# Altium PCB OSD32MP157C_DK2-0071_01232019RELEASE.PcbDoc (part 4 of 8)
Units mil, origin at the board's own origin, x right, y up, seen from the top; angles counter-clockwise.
Board outline 3976.38 x 2795.28 mil, 6 copper layers (Top Layer, Signal Layer 1, Signal Layer 2, Signal Layer 3, Signal Layer 4, Bottom Layer), stack 61.268 mil thick; 404 components, 418 nets, 1720 pads, 1233 vias.
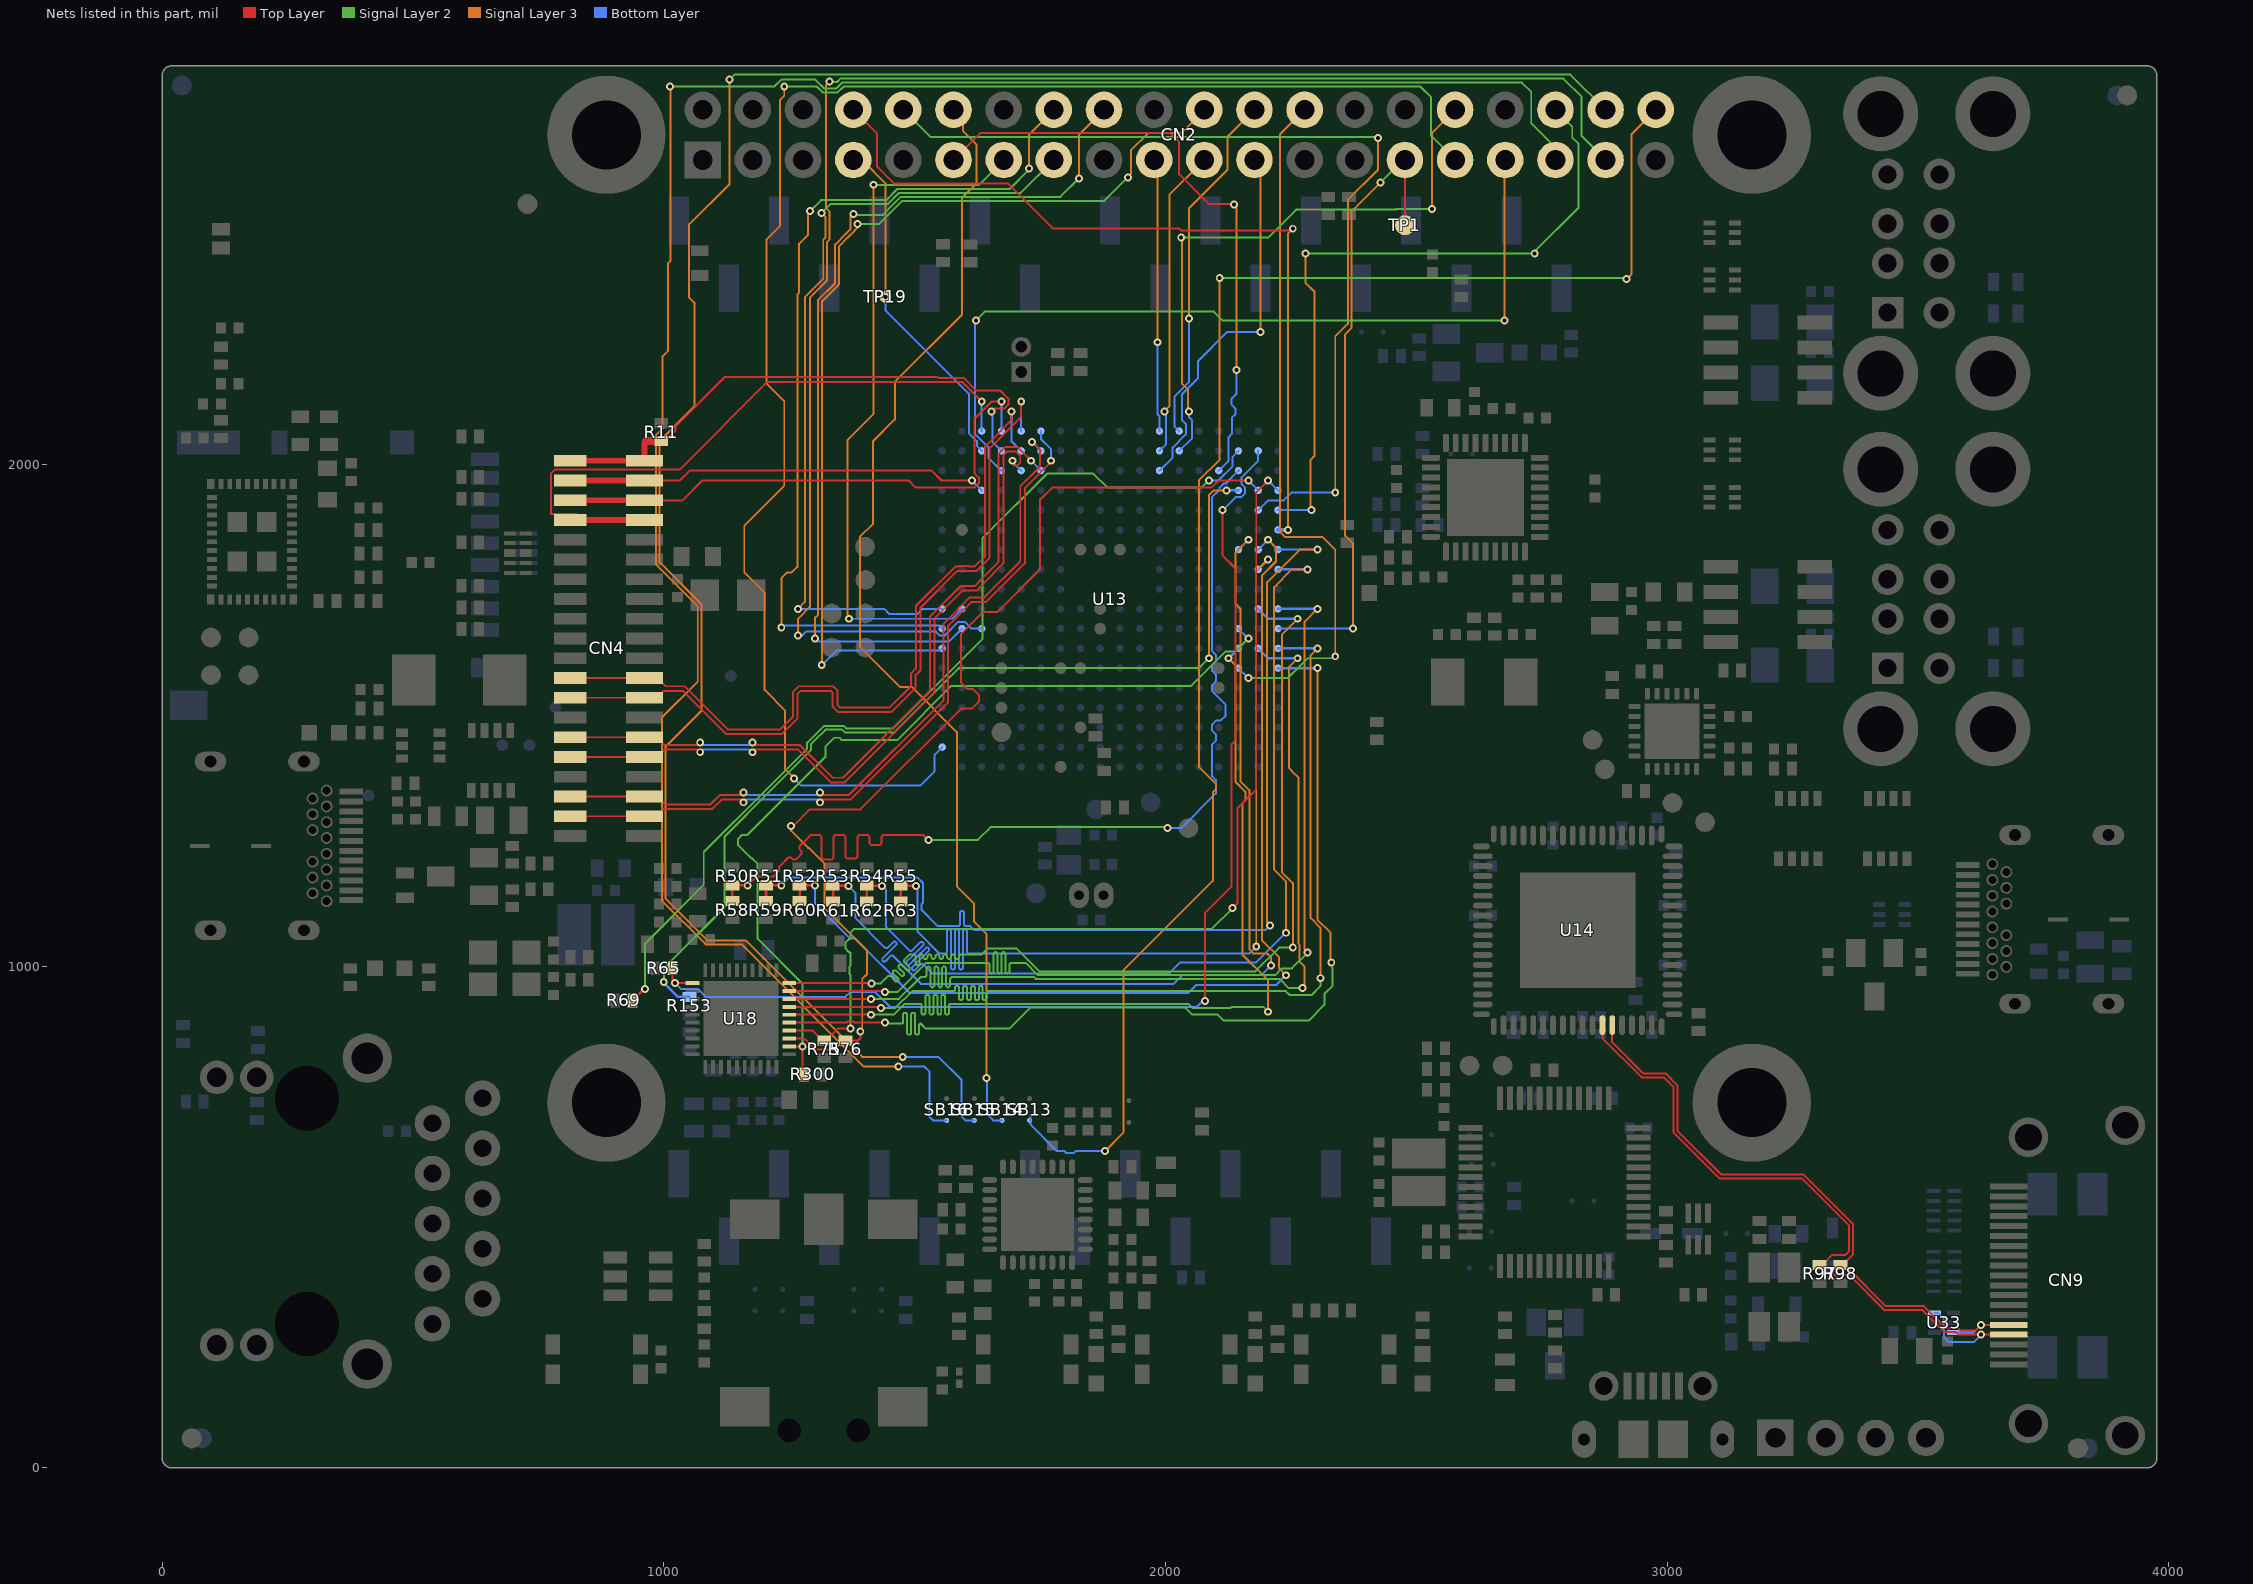
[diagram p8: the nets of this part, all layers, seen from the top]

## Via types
v1: diameter 15.75, hole 7.87, Top Layer to Bottom Layer, tented both sides, 803 vias
v2: diameter 23.62, hole 11.81, Top Layer to Bottom Layer, tented both sides, 417 vias
v3: diameter 15.75, hole 7.87, Top Layer to Bottom Layer, 13 vias

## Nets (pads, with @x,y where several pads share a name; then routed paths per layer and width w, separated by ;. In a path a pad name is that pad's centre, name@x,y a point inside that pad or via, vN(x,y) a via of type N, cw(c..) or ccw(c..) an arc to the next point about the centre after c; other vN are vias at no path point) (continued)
DSCL: CN9.15 R98.1 U14.49 U33.3 | length 1273.2
  Top Layer w3.94: U14.49@2890.75,882.87 2890.75,848.43 2952.76,786.42 2997.05,786.42 3020.67,762.8 3020.67,672.55 3108.58,584.65 3272.5,584.65 3371.06,486.08 3371.06,426.18 3349.41,404.53 R98.1@3345.47,404.53 3345.47,396.65 3362.51,396.65 3436.33,322.83 3512.12,322.83 3556.41,278.54 3580.03,278.54 3584.95,273.62 3614.17,273.62 v1(3625.98,285.43) CN9.15@3681.1,285.43
  Bottom Layer w3.94: U33.3@3570.87,269.69 3610.24,269.69 v1(3625.98,285.43)
DSDA: CN9.16 R97.1 U14.48 U33.6 | length 1425.2
  Top Layer w3.94: U14.48@2871.06,882.87 2871.06,856.98 2949.5,778.54 2993.79,778.54 3012.8,759.53 3012.8,669.29 3105.31,576.77 3269.24,576.77 3363.19,482.82 3363.19,432.09 3355.31,424.21 3328.74,424.21 3309.06,404.53 R97.1@3304.13,404.53 3322.83,385.83 3362.2,385.83 3433.07,314.96 3508.86,314.96 3553.15,270.67 3576.77,270.67 3581.69,265.75 v1(3625.98,265.75) CN9.16@3681.1,265.75
  Bottom Layer w3.94: U33.6@3533.46,309.06 3539.85,309.06 3552.17,296.74 3552.17,260.83 3562.01,250.98 3611.22,250.98 v1(3625.98,265.75)
DSI_CK_N: CN4.9 CN4.10 U13.P16 | length 1494.8
  Top Layer w3.94: CN4.10@813.98,1417.32 986.35,1417.32 1000.94,1431.92 1067.61,1431.92 v1(1072.65,1426.88) ; v1(1177.04,1426.79) 1182.25,1432 1267.79,1432 1332.86,1366.93 1361.02,1366.93 1539.37,1545.28 1539.37,1692.91 1595.28,1748.82 1623.63,1748.82 1637.01,1762.2 1637.01,1762.99 1677.17,1803.15 1677.17,2018.5 1685.04,2026.38 1701.97,2026.38 1710.63,2017.72 1710.63,2003.94 1704.72,1998.03 1698.82,1998.03 1696.85,2000 1696.85,2005.91 v1(1694.88,2007.87)
  Bottom Layer w3.54: v1(1072.65,1426.88) 1078.06,1432.3 1171.53,1432.3 v1(1177.04,1426.79)
  Bottom Layer w3.94: v1(1694.88,2007.87) 1694.88,2005.91 U13.P16@1712.6,1988.19
DSI_CK_P: CN4.11 CN4.12 U13.N16 | length 1493.7
  Top Layer w3.94: CN4.12@813.98,1456.69 CN4.11@961.61,1456.69 985.98,1456.69 1001.69,1440.98 1067.06,1440.98 v1(1072.65,1446.57) ; v1(1177.04,1446.47) 1182.45,1441.06 1271.54,1441.06 1336.61,1375.98 1357.27,1375.98 1530.31,1549.03 1530.31,1696.66 1591.52,1757.87 1619.88,1757.87 1627.95,1765.95 1627.95,1766.74 1667.32,1806.11 1667.32,2021.47 1673.23,2027.37 1673.23,2027.56 1681.1,2035.43 1704.72,2035.43 v1(1732.28,2007.87) v1@1733.27,2006.89
  Bottom Layer w3.54: v1@1171.72,1441.16 v1(1177.04,1446.47)
  Bottom Layer w3.94: v1(1072.65,1446.57) 1078.06,1441.16 v1@1171.72,1441.16 ; v1(1732.28,2007.87) v1@1736.22,2003.94 ; v1@1736.22,2009.84 1736.22,2007.87 v1@1736.22,2003.94 ; U13.N16@1751.97,1988.19 v1@1736.22,2003.94
DSI_D0_N: CN4.15 CN4.16 U13.P18 | length 1587.1
  Top Layer w3.94: CN4.16@813.98,1535.43 CN4.15@961.61,1535.43 986.33,1535.43 1000.2,1549.3 1037.7,1549.3 1123.61,1463.39 1236.03,1463.39 1266.93,1494.28 1266.93,1543.49 1272.73,1549.3 1332.59,1549.3 1336.61,1545.28 1336.61,1517.72 1347.64,1506.69 1453.54,1506.69 1501.97,1555.12 1501.97,1580.51 1511.81,1590.35 1511.81,1714.57 1585.43,1788.19 1623.63,1788.19 1649.61,1814.16 1649.61,2032.47 1712.6,2095.46 v1(1712.6,2125.98)
  Bottom Layer w3.94: U13.P18@1712.6,2066.93 v1(1712.6,2125.98)
DSI_D0_P: CN4.17 CN4.18 U13.P17 | length 1578.8
  Top Layer w3.94: CN4.18@813.98,1574.8 CN4.17@961.61,1574.8 987.5,1574.8 1003.95,1558.35 1041.45,1558.35 1127.36,1472.44 1232.28,1472.44 1257.87,1498.03 1257.87,1547.24 1268.98,1558.35 1338.58,1558.35 1338.58,1557.09 1346.46,1549.21 1346.46,1520.68 1351.39,1515.75 1449.79,1515.75 1492.91,1558.87 1492.91,1584.26 1502.76,1594.1 1502.76,1718.32 1581.68,1797.24 1587.59,1797.24 1588.18,1797.84 1607.87,1797.84 1608.47,1797.24 1619.88,1797.24 1640.55,1817.91 1640.55,2036.22 1692.91,2088.58 v1(1692.91,2106.3)
  Bottom Layer w3.94: v1(1692.91,2106.3) 1692.91,2047.24 U13.P17@1712.6,2027.56
DSI_D1_N: CN4.3 CN4.4 U13.N18 | length 1506
  Top Layer w3.94: CN4.4@813.98,1299.21 CN4.3@961.61,1299.21 985.58,1299.21 1000.18,1313.81 1096.88,1313.81 1115.43,1332.36 1153.97,1332.36 v1(1159.28,1327.04) ; v1(1311.53,1327.04) 1317.17,1332.68 1373.04,1332.68 1566.93,1526.56 1566.93,1679.13 1614.17,1726.38 1642.73,1726.38 1719.68,1803.34 1719.68,1952.94 1771.65,2004.91 v1(1771.65,2007.87)
  Bottom Layer w3.94: v1(1159.28,1327.04) 1164.6,1332.36 1306.22,1332.36 v1(1311.53,1327.04) ; U13.N18@1751.97,2066.93 1751.97,2051.18 1771.65,2031.5 v1(1771.65,2007.87)
DSI_D1_P: CN4.5 CN4.6 U13.N17 | length 1493.3
  Top Layer w3.94: CN4.6@813.98,1338.58 CN4.5@961.61,1338.58 986.12,1338.58 1001.83,1322.87 1093.13,1322.87 1111.68,1341.41 1153.97,1341.41 v1(1159.28,1346.73) ; v1(1311.53,1346.73) 1316.53,1341.73 1369.29,1341.73 1557.87,1530.31 1557.87,1682.88 1610.42,1735.43 1638.98,1735.43 1710.63,1807.09 1710.63,1956.69 1750,1996.06 1750,2029.53 v1(1734.25,2045.28) v1@1732.28,2047.24
  Bottom Layer w3.94: v1(1159.28,1346.73) 1164.6,1341.41 1306.22,1341.41 v1(1311.53,1346.73) ; v1@1732.28,2047.24 v1(1734.25,2045.28) U13.N17@1751.97,2027.56
DSI_LCD_BL_CTRL: CN4.37 CN4.38 U13.T15 | length 844.3
  Top Layer w3.94: CN4.37@961.61,1968.5 1032.17,1968.5 1051.86,1988.19 1533.96,1988.19 1553.64,1968.5 v1(1614.17,1968.5)
  Top Layer w11.81: CN4.38@813.98,1968.5 CN4.37@961.61,1968.5
  Bottom Layer w3.94: v1(1614.17,1968.5) U13.T15@1633.86,1948.82
DSI_LCD_INT: CN4.33 CN4.34 U13.T18 | length 1305.8
  Top Layer w3.94: CN4.34@813.98,1889.76 826.38,1902.17 775.59,1902.17 775.59,1982.76 782.99,1990.16 1031.5,1990.16 1206.69,2165.35 1594.49,2165.35 v1(1633.86,2125.98)
  Top Layer w11.81: CN4.34@813.98,1889.76 CN4.33@961.61,1889.76
  Bottom Layer w3.94: U13.T18@1633.86,2066.93 v1(1633.86,2125.98)
DSI_RESET: CN4.39 CN4.40 R11.2 U13.R17 | length 1124.2
  Top Layer w3.94: R11.2@995.08,2047.24 1002.37,2047.24 1023.62,2068.5 1023.62,2076.77 1122.05,2175.2 1545.28,2175.2 1547.24,2173.23 1597.75,2173.23 1623.34,2147.64 1671.26,2147.64 1687.01,2131.89 1687.01,2120.28 1678.74,2112.01 1659.25,2112.01 v1(1653.54,2106.3)
  Top Layer w11.81: CN4.40@813.98,2007.87 CN4.39@961.61,2007.87 961.61,2044.29 964.57,2047.24
  Top Layer w15.75: 964.57,2047.24 R11.2@995.08,2047.24
  Bottom Layer w3.94: v1(1653.54,2106.3) 1655.02,2104.82 1655.02,2045.77 U13.R17@1673.23,2027.56
DSI_TE: CN4.35 CN4.36 U13.R18 | length 1098.4
  Top Layer w3.94: CN4.35@961.61,1929.13 1037.4,1929.13 1076.77,1968.5 1487.98,1968.5 1501.77,1954.72 1619.88,1954.72 1627.95,1962.8 1627.95,1974.21 1619.88,1982.28 1619.88,2092.12 1653.74,2125.98 v1(1673.23,2125.98)
  Top Layer w11.81: CN4.36@813.98,1929.13 CN4.35@961.61,1929.13
  Bottom Layer w3.94: U13.R18@1673.23,2066.93 v1(1673.23,2125.98)
ETH_CLK: R69.2 U13.C17 | length 1915.6
  Top Layer w5.12: R69.2@937.99,932.09 960.63,954.72 v1(962.6,954.72)
  Signal Layer 2 w3.94: v1(962.6,954.72) 962.6,1045.27 1079.72,1162.4 1079.72,1228 1205.12,1353.39 1285.83,1434.1 1285.83,1445.81 1319.54,1479.53 1358.56,1479.53 1363.68,1474.41 1457.11,1474.41 1635.83,1653.12 1635.83,1854.13 1763.98,1982.28 1856.1,1982.28 1858.07,1980.31 1858.47,1980.31 1884.06,1954.72 2072.83,1954.72 v1(2086.61,1968.5)
  Bottom Layer w3.94: v1(2086.61,1968.5) 2105.41,1968.5 2133.86,1996.96 2133.86,2015.75 U13.C17@2145.67,2027.56
ETH_CLK125: R153.1 U13.C15 | length 1916.8
  Signal Layer 2 w3.94: v1(1000,968.5) 1000,996.26 1121.06,1117.32 1121.06,1258.76 1212.6,1350.29 1293.46,1431.15 1293.31,1431.3 1293.31,1442.72 1301.38,1450.79 1322.64,1472.05 1355.46,1472.05 1360.97,1466.54 1459.82,1466.54 1587.77,1594.49 2066.93,1594.49 v1(2086.61,1614.17)
  Signal Layer 3 w3.94: v1(2086.61,1614.17) 2086.61,1938.98 2096.46,1948.82 v1(2122.05,1948.82)
  Bottom Layer w5.12: v1(1000,968.5) 1000,967.17 1028.2,938.98 R153.1@1051.18,938.98 ; v1(2122.05,1948.82) U13.C15@2145.67,1948.82
ETH_GTX_CLK: U13.B9 U18.20 | length 2038.4
  Top Layer w3.94: U18.20@1250,966.54 1413.89,966.54 v1(1414.28,966.14)
  Signal Layer 2 w3.94: v1(1414.28,966.14) 1432.68,966.14 1440.94,974.41 1443.73,977.19 1447.35,980.81 1451.25,980.81 1462.38,969.68 1466.28,969.68 1467.95,971.35 1467.95,975.24 1456.81,986.38 1456.81,990.28 1458.48,991.95 1462.38,991.95 1473.52,980.81 1477.41,980.81 1479.08,982.48 1479.08,986.38 1467.95,997.52 1467.95,1001.41 1469.62,1003.08 1473.52,1003.08 1484.65,991.95 1488.55,991.95 1490.22,993.62 1490.22,997.52 1479.08,1008.65 1479.08,1012.55 1482.7,1016.17 1488.27,1021.74 1490.16,1023.62 1494.09,1023.62 1499.21,1023.62 1501.97,1020.87 1501.97,1005.12 1504.72,1002.36 1507.09,1002.36 1509.84,1005.12 1509.84,1020.87 1512.6,1023.62 1514.96,1023.62 1517.72,1020.87 1517.72,1017.31 1520.47,1014.55 1522.83,1014.55 1525.59,1017.31 1525.59,1020.87 1528.35,1023.62 1530.71,1023.62 1533.46,1020.87 1533.46,1017.32 1536.22,1014.57 1538.58,1014.57 1541.34,1017.32 1541.34,1020.87 1544.09,1023.62 1546.46,1023.62 1549.21,1020.87 1549.21,1017.32 1551.97,1014.57 1554.33,1014.57 1557.09,1017.32 1557.09,1020.87 1559.84,1023.62 1562.2,1023.62 1564.96,1020.87 1564.96,1017.32 1567.72,1014.57 1570.08,1014.57 1572.83,1017.32 1572.83,1020.87 1575.59,1023.62 1577.95,1023.62 1580.71,1020.87 1580.71,1017.32 1583.46,1014.57 1585.83,1014.57 1588.58,1017.32 1588.58,1020.87 1591.34,1023.62 1596.46,1023.62 1633.86,1023.62 1646.06,1035.83 1703.1,1035.83 1748.77,990.16 2179.53,990.16 2226.77,1037.4 v1(2253.94,1037.4)
  Signal Layer 3 w3.94: v1(2253.94,1037.4) 2253.94,1166.09 2232.28,1187.74 2232.28,1661.42 v1(2263.78,1692.91)
  Bottom Layer w5.12: U13.B9@2185.04,1712.6 2204.72,1692.91 v1(2263.78,1692.91)
ETH_MDC: R76.1 U13.B15 U18.13 | length 2091.9
  Top Layer w3.94: U18.13@1250,856.3 1276.57,856.3 1278.54,854.33 1282.28,854.33 1301.97,834.65 1340.55,834.65 1358.27,852.36 R76.1@1365.16,852.36 ; v1@1257.87,1279.53 1291.34,1312.99 1391.73,1312.99 1592.72,1513.98 1614.17,1513.98 1627.95,1527.76 1627.95,1541.14 1615.94,1553.15 1605.2,1553.15 1592.91,1565.44 1592.91,1662.99 1636.62,1706.69 1665.35,1706.69 1750,1791.34 1750,1929.75 1774.97,1954.72 2092.32,1954.72 2106.1,1968.5 v1(2165.35,1968.5) ; R76.1@1362.2,852.36 1387.8,852.36 1391.73,856.3 v1(1391.73,870.08)
  Signal Layer 3 w3.94: v1(1253.94,1279.53) 1253.94,1269.88 1287.6,1236.22 1288.83,1236.22 1320.87,1204.19 1320.87,1115.94 1405.51,1031.3 1405.51,984.79 1395.67,974.95 1395.67,874.02 v1(1391.73,870.08)
  Bottom Layer w3.94: v1(2165.35,1968.5) U13.B15@2185.04,1948.82
ETH_MDINT: R65.1 U13.B17 U18.31 | length 2331.4
  Top Layer w3.94: R65.1@1017.72,996.06 1017.72,971.46 v1(1022.64,966.54) U18.31@1057.09,966.54 ; v1(2078.76,931.1) 2078.76,1106.12 2131.89,1159.25 2131.89,1443.11 2139.76,1450.99 2139.76,1793.11 2114.17,1818.7 v1(2114.17,1909.45)
  Bottom Layer w3.94: v1(1022.64,966.54) 1034.25,954.92 1067.41,954.92 1083.35,938.98 1362.2,938.98 1372.05,948.82 1421.46,948.82 1450.99,919.29 2063.01,919.29 2076.79,933.07 v1(2078.76,931.1) ; v1(2114.17,1909.45) 2114.17,1909.54 2140.17,1935.53 2151.17,1935.53 2158.96,1943.32 2158.96,1954.32 2151.57,1961.7 2151.57,1974.41 2185.04,2007.87 U13.B17@2185.04,2027.56 U13.B17@2185.04,2028.35
ETH_MDIO: R75.1 U13.A15 U18.14 | length 2034.6
  Top Layer w3.94: U18.14@1250,872.05 1297.24,872.05 1316.93,852.36 R75.1@1319.88,852.36 1322.83,852.36 1346.45,875.98 v1(1372.04,875.98) ; v1(2133.86,1116.14) 2143.7,1125.98 2143.7,1314.96 2167.32,1338.58 2181.1,1352.36 2181.1,1944.88 v1(2204.72,1968.5)
  Signal Layer 2 w3.94: v1(1372.04,875.98) 1372.04,982.82 1370.08,984.79 1370.08,999.46 1372.04,1001.43 1372.04,1027.56 1370.28,1027.56 1362.2,1035.63 1362.2,1047.05 1370.28,1055.12 1372.04,1055.12 1372.04,1066.93 1379.92,1074.8 2092.72,1074.8 2133.86,1115.94 v1(2133.86,1116.14)
  Bottom Layer w3.94: v1(2204.72,1968.5) U13.A15@2224.41,1948.82
ETH_NRST: R300.2 U13.C8 U18.12 | length 1778.1
  Top Layer w3.94: U18.12@1250,840.55 v1(1276.57,840.55) 1276.57,787.4 R300.2@1279.53,784.45
  Signal Layer 2 w3.94: v1(1276.57,840.55) 1276.57,965.16 1187.01,1054.72 1187.01,1204.19 1176.63,1214.57 1175.39,1214.57 1147.64,1242.32 1147.64,1253.74 1155.71,1261.81 1166.34,1261.81 1322.83,1418.3 1322.83,1438.78 1339.76,1455.71 1350.64,1455.71 1355.17,1451.18 1465.62,1451.18 1573.49,1559.06 2051.38,1559.06 2120.28,1627.95 2139.76,1627.95 v1(2165.35,1653.54)
  Bottom Layer w3.94: U13.C8@2145.67,1673.23 v1(2165.35,1653.54)
ETH_RX_CLK: R50.2 R58.1 U13.C16 | length 2029.5
  Top Layer w3.94: v1(1167.32,1161.42) 1185.04,1179.13 1218.19,1179.13 1230.01,1190.94 1230.01,1198.51 1234.07,1202.57 1248.45,1216.96 1253.53,1216.96 1257.69,1212.79 1262.77,1212.79 1274.62,1224.64 1274.62,1229.72 1270.46,1233.88 1270.46,1238.96 1284.84,1253.35 1293.31,1261.81 1310.66,1261.81 1314.25,1258.22 1314.25,1216.38 1317.84,1212.79 1334.6,1212.79 1338.19,1216.38 1338.19,1258.22 1341.78,1261.81 1358.54,1261.81 1362.13,1258.22 1362.13,1218.16 1365.72,1214.57 1382.47,1214.57 1386.06,1218.16 1386.06,1258.22 1389.65,1261.81 1406.41,1261.81 1410,1258.22 1410,1245.22 1413.59,1241.63 1430.35,1241.63 1433.94,1245.22 1433.94,1258.22 1437.53,1261.81 1457.87,1261.81 1481.81,1261.81 1505.75,1261.81 1517.72,1261.81 v1(1527.56,1251.97)
  Top Layer w5.12: R58.1@1136.81,1129.92 R50.2@1136.81,1161.42 v1(1167.32,1161.42)
  Signal Layer 2 w3.94: v1(1527.56,1251.97) 1626.18,1251.97 1651.77,1277.56 2001.97,1277.56 v1(2003.94,1275.59)
  Signal Layer 3 w3.94: v1(1167.32,1161.42) v1@1167.32,1163.39
  Bottom Layer w3.94: v1(2003.94,1275.59) 2031.3,1275.59 2100.39,1344.69 2100.39,1371.36 2093.01,1378.74 2093.01,1442.51 2100.39,1449.89 2100.39,1462.4 2093.01,1469.78 2093.01,1481.88 2100.8,1489.67 2109.74,1489.67 2120.08,1500 2120.08,1521.46 2093.01,1548.52 2093.01,1560.62 2100.39,1568 2100.39,1581.6 2093.01,1588.98 2093.01,1599.99 2100.39,1607.37 2100.39,1620.97 2092.52,1628.85 2092.52,1934.84 2108.27,1950.59 2108.27,1954.53 2116.34,1962.6 2120.08,1962.6 U13.C16@2145.67,1988.19
ETH_RX_DV: R51.2 R59.1 U13.A12 | length 2072.3
  Top Layer w5.12: R59.1@1203.74,1129.92 R51.2@1203.74,1161.42 v1(1234.25,1161.42)
  Signal Layer 3 w3.94: v1(2208.66,1081.79) 2202.76,1087.7 2202.76,1765.75 2267.72,1830.71 v1(2303.15,1830.71)
  Bottom Layer w3.94: v1(1234.25,1161.42) 1250,1177.17 1505.71,1177.17 1516.73,1166.14 1516.73,1126.77 1513.78,1123.82 1513.78,1112.4 1545.47,1080.71 1580.71,1080.71 1582.68,1080.71 1588.19,1080.71 1590.55,1083.07 1590.55,1108.27 1592.91,1110.63 1596.06,1110.63 1598.43,1108.27 1598.43,1083.07 1600.79,1080.71 1606.3,1080.71 1610.24,1080.71 1618.11,1072.83 2199.7,1072.83 v1(2208.66,1081.79) ; U13.A12@2224.41,1830.71 v1(2303.15,1830.71)
ETH_RXD0: R52.1 R60.1 U13.B12 | length 2058.8
  Top Layer w5.12: R60.1@1270.67,1129.92 R52.1@1270.67,1161.42 v1(1301.18,1161.42)
  Signal Layer 3 w3.94: v1(2204.72,1850.39) 2220.47,1834.65 2220.47,1807.09 2192.91,1779.53 2192.91,1051.38 2226.58,1017.72 2226.58,995.86 v1(2240.16,982.28)
  Bottom Layer w3.94: v1(1301.18,1161.42) 1301.18,1125.98 1372.05,1055.12 1381.69,1055.12 1489.96,946.85 2045.28,946.85 2061.02,962.6 2220.47,962.6 v1(2240.16,982.28) ; U13.B12@2185.04,1830.71 v1(2204.72,1850.39)
ETH_RXD1: R53.1 R61.1 U13.C12 | length 2045
  Top Layer w5.12: R61.1@1337.6,1128.94 1337.6,1160.43 v1(1368.11,1160.43)
  Signal Layer 3 w3.94: v1(2165.35,1850.39) 2139.76,1824.8 2139.76,1722.44 2149.61,1712.6 2149.61,1368.85 2167.32,1351.13 2167.32,1045.47 2167.52,1045.28 2167.32,1045.08 2167.32,1033.66 2175.39,1025.59 2202.76,1025.59 2210.83,1017.52 v1(2210.83,1001.97)
  Bottom Layer w3.94: v1(1368.11,1160.43) 1381.89,1146.65 1381.89,1096.46 1439.96,1038.39 1442.09,1036.26 1445.43,1036.26 1458.45,1049.28 1461.79,1049.28 1464.02,1047.06 1464.02,1043.72 1449.33,1029.02 1435.52,1015.21 1435.52,1011.87 1437.74,1009.64 1441.08,1009.64 1453.22,1021.78 1456.56,1021.78 1457.68,1020.67 1513.78,964.57 2015.75,964.57 2033.46,982.28 2191.14,982.28 v1(2210.83,1001.97)
  Bottom Layer w5.12: U13.C12@2145.67,1830.71 v1(2165.35,1850.39)
ETH_RXD2: R54.2 R62.1 U13.A11 | length 2055.1
  Top Layer w5.12: R62.1@1404.53,1128.94 1404.53,1160.43 v1(1435.04,1160.43)
  Signal Layer 3 w3.94: v1(2240.16,1066.93) 2240.16,1169.29 2216.54,1192.91 2216.54,1755.91 2251.97,1791.34 v1(2283.46,1791.34)
  Bottom Layer w3.94: v1(1435.04,1160.43) 1436.02,1160.43 1442.91,1153.54 1442.91,1078.74 1490.16,1031.5 1490.99,1030.66 1494.33,1030.66 1512.28,1048.61 1515.62,1048.61 1517.85,1046.38 1517.85,1043.04 1498.23,1023.42 1483.53,1008.73 1483.53,1005.39 1485.76,1003.16 1489.1,1003.16 1503.8,1017.86 1523.41,1037.47 1526.75,1037.47 1528.98,1035.25 1528.98,1031.9 1509.36,1012.29 1494.67,997.59 1494.67,994.25 1496.9,992.03 1500.24,992.03 1513.26,1005.05 1516.6,1005.05 1517.72,1003.94 1535.43,986.22 2007.87,986.22 2029.53,1007.87 2181.1,1007.87 v1(2240.16,1066.93)
  Bottom Layer w5.12: U13.A11@2224.41,1791.34 v1(2283.46,1791.34)
ETH_RXD3: R55.1 R63.1 U13.B11 | length 2059.7
  Top Layer w5.12: R63.1@1472.44,1128.94 1472.44,1160.43 v1(1502.95,1160.43)
  Signal Layer 3 w3.94: v1(2181.1,1039.37) 2181.1,1787.4 v1(2204.72,1811.02)
  Bottom Layer w3.94: v1(1502.95,1160.43) 1505.91,1157.48 1505.91,1068.9 1549.21,1025.59 1559.06,1025.59 1562.6,1025.59 1564.96,1027.95 1564.96,1070.87 1567.32,1073.23 1570.47,1073.23 1572.83,1070.87 1572.83,1025.59 1572.83,996.06 1575.2,993.7 1578.35,993.7 1580.71,996.06 1580.71,1025.59 1580.71,1070.87 1583.07,1073.23 1586.22,1073.23 1588.58,1070.87 1588.58,1025.59 1588.58,996.06 1590.94,993.7 1594.09,993.7 1596.46,996.06 1596.46,1025.59 1596.46,1070.87 1598.82,1073.23 1601.97,1073.23 1604.33,1070.87 1604.33,1027.95 1606.69,1025.59 1608.27,1025.59 2167.32,1025.59 v1(2181.1,1039.37)
  Bottom Layer w5.12: U13.B11@2185.04,1791.34 v1(2204.72,1811.02)
ETH_TX_EN: U13.A9 U18.19 | length 2057.2
  Top Layer w3.94: U18.19@1250,950.79 v1@1438.98,950.79
  Top Layer w5.12: v1@1438.98,950.79 v1(1440.94,948.82)
  Signal Layer 2 w3.94: v1(1440.94,948.82) 1465.01,948.82 1523.28,1007.09 1643.7,1007.09 1646.85,1007.09 1649.61,1004.33 1649.61,988.58 1652.36,985.83 1654.72,985.83 1657.48,988.58 1657.48,1007.09 1657.48,1025.59 1660.24,1028.35 1662.6,1028.35 1665.35,1025.59 1665.35,1007.09 1665.35,988.58 1668.11,985.83 1670.47,985.83 1673.23,988.58 1673.23,1007.09 1673.23,1025.59 1675.98,1028.35 1678.35,1028.35 1681.1,1025.59 1681.1,1007.09 1681.1,988.58 1683.86,985.83 1686.22,985.83 1688.98,988.58 1688.98,1004.33 1691.73,1007.09 1692.91,1007.09 1721.26,1007.09 1745.67,982.68 2218.9,982.68 2232.28,996.06 2251.97,996.06 v1(2283.46,1027.56)
  Signal Layer 3 w3.94: v1(2283.46,1027.56) 2277.56,1033.46 2277.56,1687.01 v1(2303.15,1712.6)
  Bottom Layer w5.12: U13.A9@2224.41,1712.6 v1(2303.15,1712.6)
ETH_TXD0: U13.B7 U18.18 | length 2042.4
  Top Layer w3.94: U18.18@1250,935.04 v1(1413.39,935.04)
  Signal Layer 2 w3.94: v1(1413.39,935.04) 1468.5,935.04 1511.81,978.35 1517.72,978.35 1520.87,978.35 1523.62,981.1 1523.62,996.85 1526.38,999.61 1528.74,999.61 1531.5,996.85 1531.5,978.35 1531.5,961.02 1534.25,958.27 1536.61,958.27 1539.37,961.02 1539.37,978.35 1539.37,996.85 1542.13,999.61 1544.49,999.61 1547.24,996.85 1547.24,978.35 1547.24,961.02 1550,958.27 1552.36,958.27 1555.12,961.02 1555.12,978.35 1555.12,996.85 1557.87,999.61 1560.24,999.61 1562.99,996.85 1562.99,978.35 1562.99,961.02 1565.75,958.27 1568.11,958.27 1570.87,961.02 1570.87,975.59 1573.62,978.35 1574.8,978.35 1738.19,978.35 1741.34,975.2 2227.76,975.2 2246.26,956.69 v1(2273.62,956.69)
  Signal Layer 3 w3.94: v1(2263.78,1614.17) 2246.06,1596.46 2246.06,1395.87 2252.17,1389.76 2252.17,1389.36 2265.74,1375.78 2265.74,1045.08 2267.72,1043.11 2267.72,1008.76 2277.56,998.92 2277.56,960.63 v1(2273.62,956.69)
  Bottom Layer w5.12: U13.B7@2185.04,1633.86 2204.72,1614.17 v1(2263.78,1614.17)
ETH_TXD1: U13.A7 U18.17 | length 2052.3
  Top Layer w3.94: U18.17@1250,919.29 v1@1431.1,919.29
  Top Layer w5.12: v1@1431.1,919.29 v1(1433.07,917.32)
  Signal Layer 2 w3.94: v1(1433.07,917.32) 1461.86,917.32 1495.33,950.79 1578.74,950.79 1580.71,952.76 1580.71,958.66 1583.07,961.03 1586.22,961.03 1588.58,958.66 1588.58,950.79 1588.58,935.04 1590.94,932.68 1594.09,932.68 1596.46,935.04 1596.46,950.79 1596.46,958.66 1598.82,961.03 1601.97,961.03 1604.33,958.66 1604.33,950.79 1604.33,935.04 1606.69,932.68 1609.84,932.68 1612.2,935.04 1612.2,950.79 1612.2,958.66 1614.57,961.03 1617.72,961.03 1620.08,958.66 1620.08,950.79 1620.08,935.04 1622.44,932.68 1625.59,932.68 1627.95,935.04 1627.95,950.79 1627.95,958.66 1630.31,961.03 1633.46,961.03 1635.83,958.66 1635.83,950.79 1635.83,935.04 1638.19,932.68 1641.34,932.68 1643.7,935.04 1643.7,948.43 1646.06,950.79 1647.64,950.79 2240.16,950.79 2248.03,942.91 2291.34,942.91 2309.06,960.63 v1(2309.06,976.38)
  Signal Layer 3 w3.94: v1(2303.15,1633.86) 2289.37,1620.08 2289.37,1096.46 2309.06,1076.77 v1(2309.06,976.38)
  Bottom Layer w5.12: U13.A7@2224.41,1633.86 v1(2303.15,1633.86)
ETH_TXD2: U13.C7 U18.16 | length 1997.1
  Top Layer w3.94: U18.16@1250,903.54 v1(1413.39,903.54)
  Signal Layer 2 w3.94: v1(1413.39,903.54) 1458.66,903.54 1480.31,925.2 1511.81,925.2 1513.78,923.23 1513.78,906.3 1516.14,903.94 1519.29,903.94 1521.65,906.3 1521.65,925.2 1521.65,940.95 1524.02,943.31 1527.17,943.31 1529.53,940.95 1529.53,925.2 1529.53,906.3 1531.89,903.94 1535.04,903.94 1537.4,906.3 1537.4,925.2 1537.4,940.95 1539.76,943.31 1542.91,943.31 1545.28,940.95 1545.28,925.2 1545.28,906.3 1547.64,903.94 1550.79,903.94 1553.15,906.3 1553.15,925.2 1553.15,940.95 1555.51,943.31 1558.66,943.31 1561.02,940.95 1561.02,925.2 1561.02,906.3 1563.39,903.94 1566.54,903.94 1568.9,906.3 1568.9,922.83 1571.26,925.2 1572.83,925.2 2045.69,925.2 2053.56,917.32 2130,917.32 2131.97,919.29 2194.88,919.29 v1(2204.72,909.45)
  Signal Layer 3 w3.94: v1(2125.98,1614.17) 2139.76,1600.39 2139.76,1368.11 2159.45,1348.43 2159.45,1330.91 2153.54,1325 2153.54,1023.62 2204.72,972.44 v1(2204.72,909.45)
  Bottom Layer w5.12: v1@2125.98,1618.11 2129.92,1618.11 U13.C7@2145.67,1633.86
ETH_TXD3: U13.A6 U18.15 | length 2044.6
  Top Layer w3.94: U18.15@1250,887.8 1364.37,887.8 1366.34,889.76 1377.75,889.76 1379.72,887.8 v1(1440.94,887.8)
  Signal Layer 2 w3.94: v1(1440.94,887.8) 1442.91,885.83 1472.44,885.83 1475.79,885.83 1477.36,887.4 1477.36,905.51 1478.94,907.09 1483.66,907.09 1485.24,905.51 1485.24,885.83 1485.24,866.14 1486.81,864.57 1491.54,864.57 1493.11,866.14 1493.11,885.83 1493.11,905.51 1494.69,907.09 1499.41,907.09 1500.98,905.51 1500.98,885.83 1500.98,866.14 1502.56,864.57 1507.28,864.57 1508.86,866.14 1508.86,884.25 1510.43,885.83 1512.8,885.83 1512.8,885.04 1521.85,875.98 1688.97,875.98 1730.71,917.72 2039.37,917.72 2053.54,903.54 2104.13,903.54 2115.94,891.73 2285.43,891.73 2316.93,923.23 2316.93,944.88 2332.68,960.63 2332.68,1005.91 v1(2330.71,1007.87)
  Signal Layer 3 w3.94: v1(2303.15,1594.49) 2303.15,1093.26 2328.74,1067.67 2328.74,1009.84 v1(2330.71,1007.87)
  Bottom Layer w5.12: U13.A6@2224.41,1594.49 v1(2303.15,1594.49)
EXP_GPIO4: CN2.7 TP19.1 U13.T17 | length 715.6
  Signal Layer 3 w3.94: CN2.7@1377.56,2607.48 1395.47,2607.48 1441.73,2561.22 v1(1441.73,2334.65) 1441.73,2353.35 1441.93,2353.54
  Bottom Layer w3.94: v1(1441.73,2334.65) 1441.73,2308.27 1608.27,2141.73 1608.27,2062.59 1624.02,2046.85 1624.02,2037.4 U13.T17@1633.86,2027.56
EXP_GPIO5: CN2.29 TP1.1 U13.A8 | length 1272.3
  Top Layer w3.94: TP1.1@2477.36,2477.36 2477.36,2607.28 CN2.29@2477.56,2607.48
  Signal Layer 2 w3.94: v1(2429.13,2562.99) 2473.62,2607.48 CN2.29@2477.56,2607.48
  Signal Layer 3 w3.94: v1(2374.02,1673.23) 2374.02,1842.52 2358.27,1858.27 2358.27,2259.84 2371.06,2272.64 2371.06,2504.92 v1(2429.13,2562.99)
  Bottom Layer w3.94: U13.A8@2224.41,1673.23 v1(2374.02,1673.23)
EXP_GPIO6: CN2.31 U13.V2 | length 3288.3
  Signal Layer 2 w3.94: v1(1240.16,2753.94) 1304.81,2753.94 1316.62,2742.13 1346.78,2742.13 1358.6,2753.94 2507.87,2753.94 2529.53,2732.28 2529.53,2655.51 CN2.31@2577.56,2607.48
  Signal Layer 3 w3.94: v1(1240.16,2753.94) 1240.16,2735.5 1231.3,2726.64 1231.3,2475.39 1204.72,2448.82 1204.72,2162.15 1240.16,2126.72 1240.16,1957.93 1160.43,1878.2 1160.43,1785.68 1200.98,1745.13 1200.98,1550.98 1242.13,1509.84 1242.13,1392.51 v1(1259.84,1374.8)
  Bottom Layer w3.94: v1(1259.84,1374.8) 1274.4,1360.24 1305.55,1360.24 1305.82,1360.51 1317.24,1360.51 1317.51,1360.24 1511.61,1360.24 1539.37,1387.99 1539.37,1421.26 U13.V2@1555.12,1437.01
EXP_GPIO7: CN2.26 U13.C6 | length 1418.6
  Signal Layer 2 w3.94: v1(2165.35,1574.8) 2244.29,1574.8 2267.72,1598.23 2267.72,1598.43 2283.46,1614.17 2334.65,1614.17 v1(2338.58,1618.11)
  Signal Layer 3 w3.94: CN2.26@2277.56,2707.48 2228.35,2658.27 2228.35,2193.11 2228.15,2192.91 2228.15,1866.14 2237.99,1856.3 2312.99,1856.3 2338.58,1830.71 v1(2338.58,1618.11)
  Bottom Layer w3.94: U13.C6@2145.67,1594.49 v1(2165.35,1574.8)
EXP_GPIO8: CN2.24 U13.F18 | length 710.8
  Signal Layer 3 w3.94: v1(2047.24,2291.34) 2047.24,2511.74 2123.82,2588.32 2123.82,2653.74 CN2.24@2177.56,2707.48
  Bottom Layer w3.94: U13.F18@2027.56,2066.93 2017.72,2076.77 2017.72,2135.83 2047.24,2165.35 v1(2047.24,2291.34)
EXP_GPIO9: CN2.21 U13.G17 | length 639.1
  Top Layer w3.94: CN2.21@2077.56,2588.19 CN2.21@2077.56,2607.48
  Signal Layer 3 w3.94: v1(1998.03,2106.3) 2007.87,2116.14 2007.87,2537.8 CN2.21@2077.56,2607.48
  Bottom Layer w3.94: U13.G17@1988.19,2027.56 2001.48,2040.85 2001.48,2102.85 v1(1998.03,2106.3)
EXP_GPIO10: CN2.19 U13.G18 | length 552.3
  Top Layer w3.94: CN2.19@1977.56,2603.35 CN2.19@1977.56,2607.48
  Signal Layer 3 w3.94: CN2.19@1977.56,2607.48 1988.19,2596.85 1984.25,2592.91 v1(1984.25,2244.09)
  Bottom Layer w3.94: v1(1984.25,2244.09) 1984.25,2100.59 1988.19,2096.65 U13.G18@1988.19,2066.93
EXP_GPIO11: CN2.23 U13.G16 | length 747.9
  Signal Layer 3 w3.94: v1(2189.37,2264.17) CN2.23@2189.37,2607.48
  Bottom Layer w3.94: U13.G16@1988.19,1988.19 2014.27,2014.27 2014.27,2033.96 2040.85,2060.53 2040.85,2081.2 2033.46,2088.59 2033.46,2140.99 2064.96,2172.49 2064.96,2206.69 2122.44,2264.17 v1(2189.37,2264.17)
EXP_GPIO12: CN2.32 U13.F17 | length 1176.3
  Signal Layer 2 w3.94: v1(2031.5,2452.76) 2204.72,2452.76 2260.67,2508.7 2459.49,2508.7 2460.63,2509.84 v1(2531.3,2509.84)
  Signal Layer 3 w3.94: 2033.46,2444.88 2033.46,2161.28 2045.28,2149.47 2045.28,2108.26 v1(2047.24,2106.3) ; v1(2531.3,2509.84) 2531.3,2661.22 CN2.32@2577.56,2707.48
  Bottom Layer w3.94: U13.F17@2027.56,2027.56 2053.15,2053.15 2053.15,2088.58 2047.24,2094.49 v1(2047.24,2106.3)
EXP_GPIO13: CN2.33 U13.R16 | length 1712
  Signal Layer 2 w3.94: v1(1622.05,2287.4) 1639.76,2305.12 2096.46,2305.12 2114.17,2287.4 v1(2676.18,2287.4)
  Signal Layer 3 w3.94: v1(2676.18,2287.4) 2676.18,2604.92 2678.15,2606.89 CN2.33@2677.56,2607.48
  Bottom Layer w3.94: v1(1622.05,2287.4) 1620.08,2285.43 1620.08,2061.92 1647.15,2034.85 1647.15,2014.27 U13.R16@1673.23,1988.19
EXP_GPIO14: CN2.8 U13.A13 | length 1640.3
  Top Layer w3.94: CN2.8@1377.56,2707.48 1425.2,2659.84 1425.2,2594.49 1431.3,2588.39 1431.3,2588.32 1458.59,2561.02 1685.83,2561.02 1776.38,2470.47 2027.75,2470.47 2031.68,2466.54 2250,2466.54 v1(2253.94,2470.47)
  Signal Layer 3 w3.94: v1(2244.09,1870.08) 2244.09,2460.63 v1(2253.94,2470.47)
  Bottom Layer w7.87: U13.A13@2224.41,1870.08 v1(2244.09,1870.08)
EXP_GPIO15: CN2.10 U13.B14 | length 1879.6
  Signal Layer 2 w3.94: CN2.10@1477.56,2707.48 1531.3,2653.74 2421.65,2653.74 v1(2423.82,2651.57)
  Signal Layer 3 w3.94: v1(2338.58,1944.88) 2338.58,2255.91 2363.58,2280.91 2363.58,2528.08 2423.82,2588.32 v1(2423.82,2651.57)
  Bottom Layer w3.94: U13.B14@2185.04,1909.45 2204.72,1929.13 2236.22,1929.13 2251.97,1944.88 v1(2338.58,1944.88)
EXP_GPIO16: CN2.36 U13.A14 | length 1388.5
  Signal Layer 2 w3.94: v1(2279.53,2421.26) v1(2736.22,2421.26) 2736.22,2425.2 2823.82,2512.8 2823.82,2639.44 2811.02,2652.23 2811.02,2674.02 CN2.36@2777.56,2707.48
  Signal Layer 3 w3.94: v1(2279.53,2421.26) 2279.53,2362.2 2297.24,2344.49 2297.24,2017.72 2289.37,2009.84 2289.37,1911.42 v1(2291.34,1909.45)
  Bottom Layer w3.94: U13.A14@2224.41,1909.45 v1(2291.34,1909.45)
EXP_GPIO17: CN2.11 U13.D16 | length 1232.8
  Top Layer w3.94: CN2.11@1577.56,2607.48 1631.3,2661.22 2010.04,2661.22 2027.56,2643.7 2027.56,2578.74 2086.37,2519.93 2135.59,2519.93 v1(2136.46,2519.05)
  Signal Layer 3 w3.94: v1@2136.16,2519.35 v1(2136.46,2519.05) 2141.73,2513.78 v1(2141.73,2188.98)
  Bottom Layer w3.94: U13.D16@2106.3,1988.19 2125.98,2007.87 2125.98,2055.03 2132.38,2061.43 2132.38,2093.21 2139.76,2100.59 2139.76,2112.01 2131.89,2119.88 2131.89,2131.69 2141.73,2141.53 v1(2141.73,2188.98)
EXP_GPIO18: CN2.12 SB14.1 | length 2277.4
  Signal Layer 3 w3.94: CN2.12@1577.56,2707.48 1596.72,2688.32 1596.72,2665.09 1623.82,2637.99 1623.82,2561.22 1594.49,2531.89 1594.49,2299.21 1460.63,2165.35 1460.63,2090.55 1417.32,2047.24 1417.32,1882.43 1390.94,1856.05 1390.94,1636.81 1470.67,1557.09 1494.09,1557.09 1584.45,1466.73 1584.45,1159.45 1618.11,1125.79 1618.11,1089.75 1643.7,1064.17 v1(1643.7,777.56)
  Bottom Layer w3.94: v1@1648.62,779.53 1646.65,777.56 v1(1643.7,777.56) 1644.68,776.57 1644.68,704.72 1656.5,692.91 SB14.1@1674.21,692.91
EXP_GPIO19: CN2.35 SB16.1 | length 4399.8
  Signal Layer 2 w3.94: v1(1012.8,2753.94) 1220.67,2753.94 1234.45,2767.72 1302.17,2767.72 1319.88,2750 1343.52,2750 1355.33,2761.81 2710.63,2761.81 2729.33,2743.11 2729.33,2680.71 2777.56,2632.48 CN2.35@2777.56,2607.48
  Signal Layer 3 w3.94: v1(1012.8,2753.94) 1013.78,2752.95 1013.78,2406.94 1008.86,2402.02 1008.86,2226.83 997.05,2215.02 997.05,2071.85 984.25,2059.06 984.25,1801.18 1067.72,1717.72 1067.72,1567.72 996.06,1496.06 996.06,1131.21 1083.58,1043.7 1155.12,1043.7 1398.62,800.2 v1(1467.52,800.2)
  Bottom Layer w3.94: v1(1467.52,800.2) 1519.74,800.2 1529.33,790.61 1529.33,700.27 1536.68,692.91 SB16.1@1563.98,692.91
EXP_GPIO20: CN2.38 SB15.1 | length 4385
  Signal Layer 2 w3.94: v1(1131.3,2768.11) 1140.75,2777.56 2807.48,2777.56 CN2.38@2877.56,2707.48
  Signal Layer 3 w3.94: v1(1131.3,2768.11) 1131.3,2559.64 1050.2,2478.54 1050.2,2334.11 1061.02,2323.28 1061.02,2116.59 991.73,2047.3 991.73,1805.45 1075.2,1721.99 1075.2,1509.93 1003.54,1438.27 1003.54,1134.87 1087.23,1051.18 1163.98,1051.18 1395.47,819.69 v1(1476.38,819.69) v1@1476.57,819.49
  Bottom Layer w3.94: v1(1476.38,819.69) 1547.44,819.69 1593.5,773.62 1593.5,700.79 1601.38,692.91 SB15.1@1619.09,692.91
EXP_GPIO21: CN2.40 SB13.1 | length 3230.7
  Signal Layer 2 w3.94: v1(2108.27,2372.05) 2917.32,2372.05 v1(2919.29,2370.08)
  Signal Layer 3 w3.94: v1(1879.92,631.89) 1916.34,668.31 1916.34,992.37 2094.49,1170.52 2094.49,1346.65 2100.39,1352.56 2100.39,1364.17 2066.93,1397.64 2066.93,1968.7 2108.27,2010.04 v1(2108.27,2372.05) ; v1(2919.29,2370.08) 2929.13,2379.92 2929.13,2659.06 CN2.40@2977.56,2707.48
  Bottom Layer w3.94: 1731.5,704.33 1731.5,687.6 1730.12,686.22 1730.12,685.24 1783.46,631.89 1798.76,631.89 1802.7,627.95 1817.38,627.95 1821.31,631.89 v1(1879.92,631.89)
EXP_GPIO22: CN2.15 U13.V9 | length 1618.2
  Signal Layer 2 w3.94: v1(1314.17,2501.57) 1332.28,2519.69 1446.9,2519.69 1468.95,2541.73 1711.81,2541.73 CN2.15@1777.56,2607.48
  Signal Layer 3 w3.94: v1(1267.72,1712.6) 1281.5,1726.38 1281.5,2333.91 1317.91,2370.33 1317.91,2448.48 1322.83,2453.4 1322.83,2492.91 v1(1314.17,2501.57)
  Bottom Layer w3.94: v1(1267.72,1712.6) 1439.17,1712.6 1449.02,1702.76 1505.91,1702.76 1515.75,1712.6 U13.V9@1555.12,1712.6
EXP_GPIO23: CN2.16 U13.V8 | length 1794.6
  Signal Layer 2 w3.94: v1@1291.54,2504.73 v1(1291.54,2505.51) 1313.58,2527.56 1443.64,2527.56 1465.69,2549.61 1689.37,2549.61 1728.34,2588.58 v1(1728.34,2590.55)
  Signal Layer 3 w3.94: v1(1234.25,1675.2) 1234.25,1773.62 1246.06,1785.43 1254.13,1785.43 ; 1255.01,1785.43 1266.14,1796.57 1266.14,2339.71 1269.69,2343.26 1269.69,2440.89 1287.6,2458.8 1287.6,2501.57 v1(1291.54,2505.51) ; v1(1728.34,2590.55) 1728.34,2658.26 CN2.16@1777.56,2707.48
  Bottom Layer w3.94: v1(1234.25,1675.2) 1238.19,1679.13 1549.21,1679.13 U13.V8@1555.12,1673.23
EXP_GPIO24: CN2.18 U13.U8 | length 1822.3
  Signal Layer 2 w3.94: v1(1377.95,2499.8) 1379.53,2498.23 1436.58,2498.23 1472.21,2533.86 1790.75,2533.86 v1(1827.76,2570.87)
  Signal Layer 3 w3.94: v1(1301.18,1653.54) 1301.18,1694.46 1307.09,1700.37 1307.09,2327.76 1341.54,2362.21 1341.54,2438.69 1363.86,2461.02 1363.98,2461.02 1372.05,2469.1 1372.05,2493.9 v1(1377.95,2499.8) ; v1(1827.76,2570.87) 1827.76,2657.68 CN2.18@1877.56,2707.48
  Bottom Layer w3.94: v1(1301.18,1653.54) 1307.09,1647.63 1568.89,1647.63 U13.U8@1594.49,1673.23
EXP_GPIO25: CN2.22 U13.V7 | length 1977
  Signal Layer 2 w3.94: v1(1385.83,2480.12) 1429.61,2480.12 1475.47,2525.98 1878.35,2525.98 v1(1925.2,2572.83)
  Signal Layer 3 w3.94: v1(1314.96,1600.39) 1314.96,2325.06 1349.41,2359.51 1349.41,2435.43 1367.13,2453.15 1367.24,2453.15 1379.92,2465.83 1379.92,2466.54 1385.83,2472.44 v1(1385.83,2480.12) ; v1(1925.2,2572.83) 1931.3,2578.94 1931.3,2626.64 1965.88,2661.22 2031.3,2661.22 CN2.22@2077.56,2707.48
  Bottom Layer w3.94: v1(1314.96,1600.39) 1344.49,1629.92 1551.18,1629.92 U13.V7@1555.12,1633.86
EXP_GPIO26: CN2.37 U13.T8 | length 3187.9
  Signal Layer 2 w3.94: v1(1330.71,2763.78) 1331.55,2762.94 1345.33,2762.94 1352.07,2769.69 2793.31,2769.69 2829.72,2733.27 2829.72,2655.31 CN2.37@2877.56,2607.48
  Signal Layer 3 w3.94: v1(1267.72,1659.45) 1267.72,1692.91 1291.34,1716.54 1291.34,2333.17 1325.79,2367.62 1325.79,2444.1 1330.71,2449.03 1330.71,2504.53 1323.82,2511.42 1323.82,2756.89 v1(1330.71,2763.78)
  Bottom Layer w3.94: v1(1267.72,1659.45) 1275.59,1659.45 1283.46,1667.32 1542.23,1667.32 1549.61,1659.94 1560.62,1659.94 1587.2,1686.52 1599.99,1686.52 1613.28,1673.23 U13.T8@1633.86,1673.23
EXP_GPIO27: CN2.13 U13.U9 | length 1404.1
  Signal Layer 2 w3.94: v1(1418.31,2558.07) 1467.91,2558.07 1468.14,2558.3 1468.95,2557.48 1627.56,2557.48 CN2.13@1677.56,2607.48
  Signal Layer 3 w3.94: v1(1369.29,1692.91) 1372.05,1695.67 1366.14,1701.57 1366.14,2049.21 1418.31,2101.38 v1(1418.31,2558.07)
  Bottom Layer w3.94: v1(1369.29,1692.91) 1574.8,1692.91 U13.U9@1594.49,1712.6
